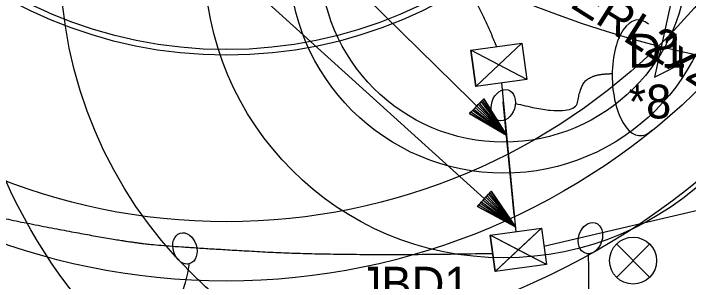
# Model space of a CAD drawing. Extents: x 1638506 to 1658005, y 834807 to 846788.
# Drawn here: x 1641220.4 to 1641459.3, y 842032.5 to 842127.5 of the extents above; entities that cross this region are included whole.
import ezdxf

# ---------------------------------------------------------------- set-up
doc = ezdxf.new("R2010")
doc.units = 0
for name, color, linetype in [('Default', 7, 'Continuous'), ('Old_Level_1', 7, 'Continuous'), ('Old_Level_4', 7, 'Continuous'), ('Scratch_Level_0', 7, 'Continuous'), ('Sheet North Arrow CELL', 7, 'Continuous')]:
    doc.layers.add(name, color=color, linetype=linetype)

msp = doc.modelspace()

# ---------------------------------------------------------------- linework, layer by layer
at = {"layer": 'Default'}
for p, q in [((1641192.01, 842284.15), (1641394.9, 842084.34)), ((1641193.58, 842237.04), (1641398.04, 842051.93)), ((1641400.39, 842117.01), (1641384.04, 842101.68)), ((1641402.16, 842104.17), (1641382.27, 842114.52)), ((1641393.1, 842102.92), (1641398.21, 842050.17)), ((1641397.62, 842056.22), (1641393.75, 842096.15)), ((1641408.15, 842045), (1641465.34, 842058.53)), ((1641407.27, 842051.42), (1641390.91, 842036.09)), ((1641409.03, 842038.58), (1641389.15, 842048.93)), ((1641433.94, 842045.74), (1641445.5, 842034.03)), ((1641445.5, 842045.74), (1641433.94, 842034.03))]:
    msp.add_line(p, q, dxfattribs=at)
for points in [[(1641402.16, 842104.17), (1641384.04, 842101.68), (1641382.27, 842114.52), (1641400.39, 842117.01)], [(1641392.22, 842109.34), (1641400.39, 842117.01), (1641402.16, 842104.17)], [(1641392.22, 842109.34), (1641382.27, 842114.52), (1641384.04, 842101.68)], [(1641409.03, 842038.58), (1641390.91, 842036.09), (1641389.15, 842048.93), (1641407.27, 842051.42)], [(1641399.09, 842043.75), (1641407.27, 842051.42), (1641409.03, 842038.58)], [(1641399.09, 842043.75), (1641389.15, 842048.93), (1641390.91, 842036.09)]]:
    msp.add_lwpolyline(points, close=True, dxfattribs=at)
for points in [[(1641384.36, 842094.72), (1641384.88, 842095.25), (1641394.9, 842084.34), (1641385.36, 842095.74), (1641385.88, 842096.26), (1641394.9, 842084.34), (1641386.4, 842096.79), (1641386.92, 842097.32), (1641394.9, 842084.34), (1641381.8, 842092.05), (1641382.28, 842092.61), (1641394.9, 842084.34), (1641382.83, 842093.1), (1641383.32, 842093.66), (1641394.9, 842084.34), (1641383.84, 842094.19), (1641386.92, 842097.32), (1641381.8, 842092.05), (1641394.9, 842084.34), (1641386.92, 842097.32)], [(1641387.07, 842061.86), (1641387.56, 842062.41), (1641398.04, 842051.93), (1641388.03, 842062.93), (1641388.52, 842063.47), (1641398.04, 842051.93), (1641389.02, 842064.02), (1641389.52, 842064.57), (1641398.04, 842051.93), (1641384.62, 842059.09), (1641385.08, 842059.67), (1641398.04, 842051.93), (1641385.61, 842060.19), (1641386.07, 842060.77), (1641398.04, 842051.93), (1641386.57, 842061.32), (1641389.52, 842064.57), (1641384.62, 842059.09), (1641398.04, 842051.93), (1641389.52, 842064.57)]]:
    msp.add_lwpolyline(points, dxfattribs=at)
msp.add_circle((1641439.72, 842039.93), 8.31, dxfattribs=at)
for centre, major_axis, ratio, start_param, end_param in [((1641441.91, 842104.72), (-0.49, 20.52), 0.466223, 5.884886, 7.853982), ((1641441.91, 842104.72), (-0.49, 20.52), 0.466223, 1.570796, 3.572354), ((1641253, 842042.24), (3.78, 34.34), 0.862742, 3.141593, 4.712389)]:
    msp.add_ellipse(centre, major_axis=major_axis, ratio=ratio, start_param=start_param, end_param=end_param, dxfattribs=at)
for centre, major_axis in [((1641393.75, 842095.02), (-1.72, -5.4)), ((1641424.63, 842047.92), (1.72, 5.4)), ((1641281.06, 842044.27), (-1.72, 5.4))]:
    msp.add_ellipse(centre, major_axis=major_axis, ratio=0.730797, dxfattribs=at)
for points in [[(1641295.68, 842243.6), (1641303.97, 842209.15), (1641349.49, 842167.37), (1641379.28, 842146.14), (1641391.33, 842115.76)], [(1641398.05, 842095.65), (1641419.24, 842090.14), (1641421.09, 842102.69), (1641426.74, 842106.18), (1641432.34, 842106.2)], [(1641114.75, 842087.65), (1641168.01, 842067.62), (1641198.18, 842058.54), (1641257.4, 842046.88), (1641278.73, 842044.73), (1641337.02, 842041.51), (1641390.03, 842042.51)]]:
    msp.add_open_spline(points, degree=2, dxfattribs=at)
msp.add_spline([(1641376.13, 841972.66), (1641421.77, 842014.09), (1641423.92, 842042.37)], degree=3, dxfattribs=at)
at = {"layer": 'Old_Level_1'}
for radius in [365, 307, 240, 158]:
    msp.add_circle((1641295.68, 842272.71), radius, dxfattribs=at)
at = {"layer": 'Old_Level_4'}
for centre, radius in [((1641538.84, 842469.72), 365), ((1641393.92, 842146.92), 219), ((1641393.92, 842146.92), 193), ((1641393.92, 842146.92), 157), ((1641393.92, 842146.92), 106), ((1641393.92, 842146.92), 76), ((1641393.92, 842146.92), 65)]:
    msp.add_circle(centre, radius, dxfattribs=at)
at = {"layer": 'Scratch_Level_0'}
for radius in [297, 264, 219, 160]:
    msp.add_circle((1641295.75, 842272.71), radius, dxfattribs=at)
at = {"layer": 'Sheet North Arrow CELL'}
msp.add_lwpolyline([(1641540.04, 842526.99), (1641447.29, 842104.99), (1641540.04, 842151.99)], close=True, dxfattribs=at)

# ---------------------------------------------------------------- texts
at = {"layer": 'Default'}
for s, p in [('D1', (1641438.07, 842108.31)), ('*8', (1641438.07, 842090.31)), ('JBD1', (1641342.6, 842025.76))]:
    msp.add_text(s, height=12, dxfattribs=at).set_placement(p)
at = {"layer": 'Scratch_Level_0'}
msp.add_text('GE ERL2x23C340', height=12, rotation=327.8202, dxfattribs=at).set_placement((1641393.41, 842144.81))

doc.saveas('drawing.dxf')
